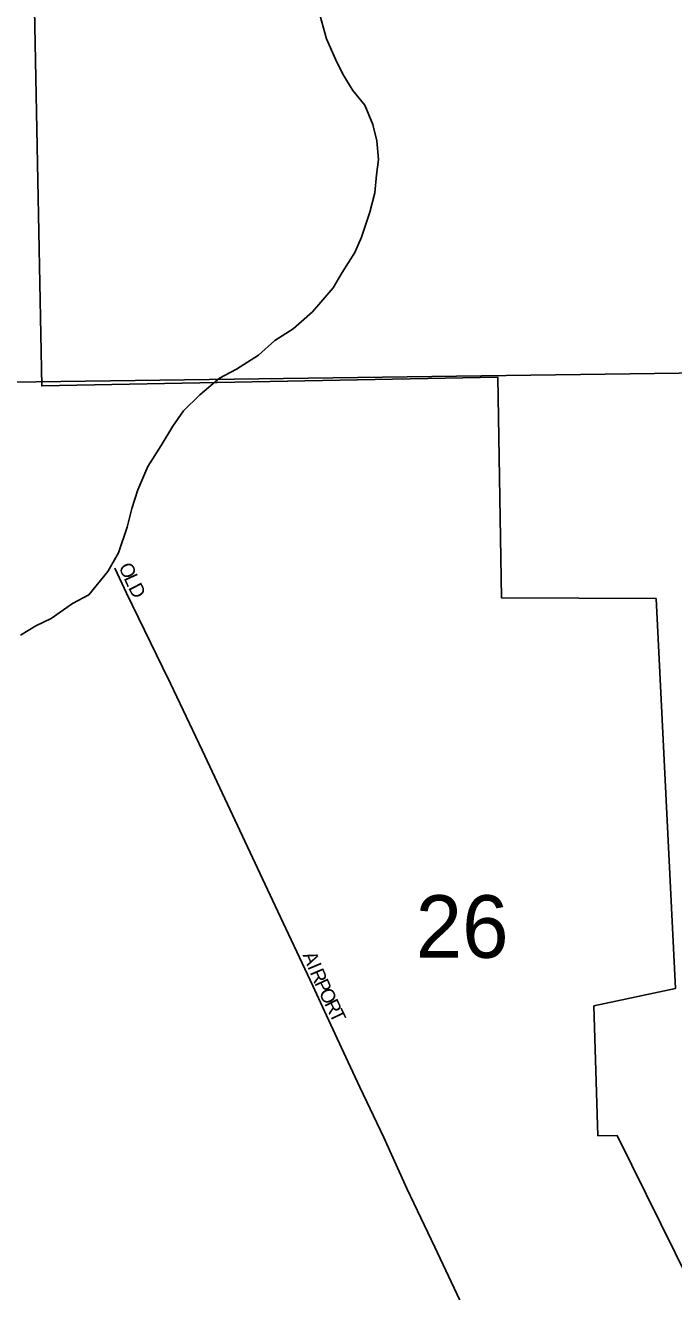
# Model space of a CAD drawing. Extents: x 1985906 to 2360102, y 891258 to 1222054.
# Drawn here: x 2131040 to 2133334, y 1032930 to 1037407 of the extents above; entities that cross this region are included whole.
import ezdxf

# ---------------------------------------------------------------- set-up
doc = ezdxf.new("R2010")
doc.units = 0
for name, color, linetype in [('GM_X_City_Street', 7, 'Continuous'), ('GM_X_City_Street_Text', 7, 'Continuous'), ('GM_X_Corporation', 7, 'Continuous'), ('GM_X_Minor_River', 7, 'Continuous'), ('GM_X_Section', 7, 'Continuous'), ('GM_X_Section_Text', 7, 'Continuous')]:
    doc.layers.add(name, color=color, linetype=linetype)

msp = doc.modelspace()

# ---------------------------------------------------------------- linework, layer by layer
at = {"layer": 'GM_X_City_Street'}
msp.add_lwpolyline([(2132840.6, 1032342.7), (2132825.7, 1032373.2), (2132767, 1032493.3), (2132696, 1032650.2), (2132614.6, 1032819.3), (2132489.3, 1033087.5), (2132390.2, 1033295.4), (2132308.2, 1033474.9), (2132223.7, 1033653.4), (2132173.6, 1033759.7), (2132098.5, 1033921.7), (2132057.5, 1034011.4), (2131923.9, 1034294), (2131826.6, 1034502.8), (2131665.5, 1034845.1), (2131553.7, 1035080.4), (2131525.2, 1035138.6), (2131398.2, 1035400.3), (2131357.3, 1035488.2)], dxfattribs=at)
at = {"layer": 'GM_X_Corporation'}
msp.add_lwpolyline([(2131070.6, 1037586.4), (2131098.6, 1036132.6), (2132711.3, 1036163.6), (2132724.1, 1035383.6), (2133271.5, 1035380.9), (2133339.5, 1034001.5), (2133051.2, 1033940.1), (2133065.8, 1033481.1), (2133133.4, 1033481.9), (2133390.9, 1032963)], dxfattribs=at)
at = {"layer": 'GM_X_Minor_River'}
msp.add_lwpolyline([(2131023.7, 1035251.4), (2131077.5, 1035283.8), (2131131.3, 1035310.3), (2131206.9, 1035362.9), (2131264.7, 1035393.4), (2131332.1, 1035476), (2131369.7, 1035542.4), (2131401, 1035632.7), (2131416.6, 1035698.9), (2131438.1, 1035765.2), (2131473.5, 1035847.5), (2131521, 1035922), (2131562.6, 1035990.4), (2131600.2, 1036044.7), (2131657.8, 1036101.2), (2131727.4, 1036159.8), (2131787.1, 1036192.3), (2131864.8, 1036241), (2131922.4, 1036293.4), (2131988.1, 1036334), (2132055.7, 1036394.6), (2132129.1, 1036479.2), (2132160.7, 1036533.5), (2132206.2, 1036604), (2132229.9, 1036658.2), (2132259.3, 1036746.6), (2132276.8, 1036814.8), (2132282.4, 1036878.9), (2132290, 1036933), (2132283.5, 1036999.1), (2132269.1, 1037057), (2132240.7, 1037124.9), (2132198.3, 1037176.7), (2132163.9, 1037234.5), (2132137.6, 1037288.3), (2132105.1, 1037360.2), (2132082.5, 1037444.1)], dxfattribs=at)
at = {"layer": 'GM_X_Section'}
for points in [[(2130109.5, 1041463.5), (2135234.2, 1041549.5), (2135365.6, 1036205), (2130202.8, 1036134.8)], [(2130202.8, 1036134.8), (2135365.6, 1036205), (2135418, 1033901.9), (2135499.1, 1030852.6), (2130280.1, 1030804)]]:
    msp.add_lwpolyline(points, close=True, dxfattribs=at)

# ---------------------------------------------------------------- texts
at = {"layer": 'GM_X_City_Street_Text'}
for s, rotation, p in [('O', 294.5706, (2131369.1, 1035493.5)), ('L', 294.5729, (2131387.4, 1035453.4)), ('D', 297.4312, (2131403.2, 1035419)), ('A', 292.6619, (2132020.4, 1034120.5)), ('I', 292.7028, (2132037.3, 1034079.8)), ('R', 292.9446, (2132045.9, 1034059.3)), ('P', 294.9143, (2132062.1, 1034021.1)), ('O', 295.9354, (2132077.4, 1033988.3)), ('R', 295.9973, (2132096.6, 1033948.7)), ('T', 295.9662, (2132114, 1033913.1))]:
    msp.add_text(s, height=50, rotation=rotation, dxfattribs=at).set_placement(p)
at = {"layer": 'GM_X_Section_Text'}
msp.add_text('26', height=221, rotation=0, dxfattribs=at).set_placement((2132420.9, 1034110.6))

doc.saveas('drawing.dxf')
